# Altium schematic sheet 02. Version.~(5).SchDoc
size A3; DocumentNumber: 2; SheetNumber: 2; SheetTotal: 2
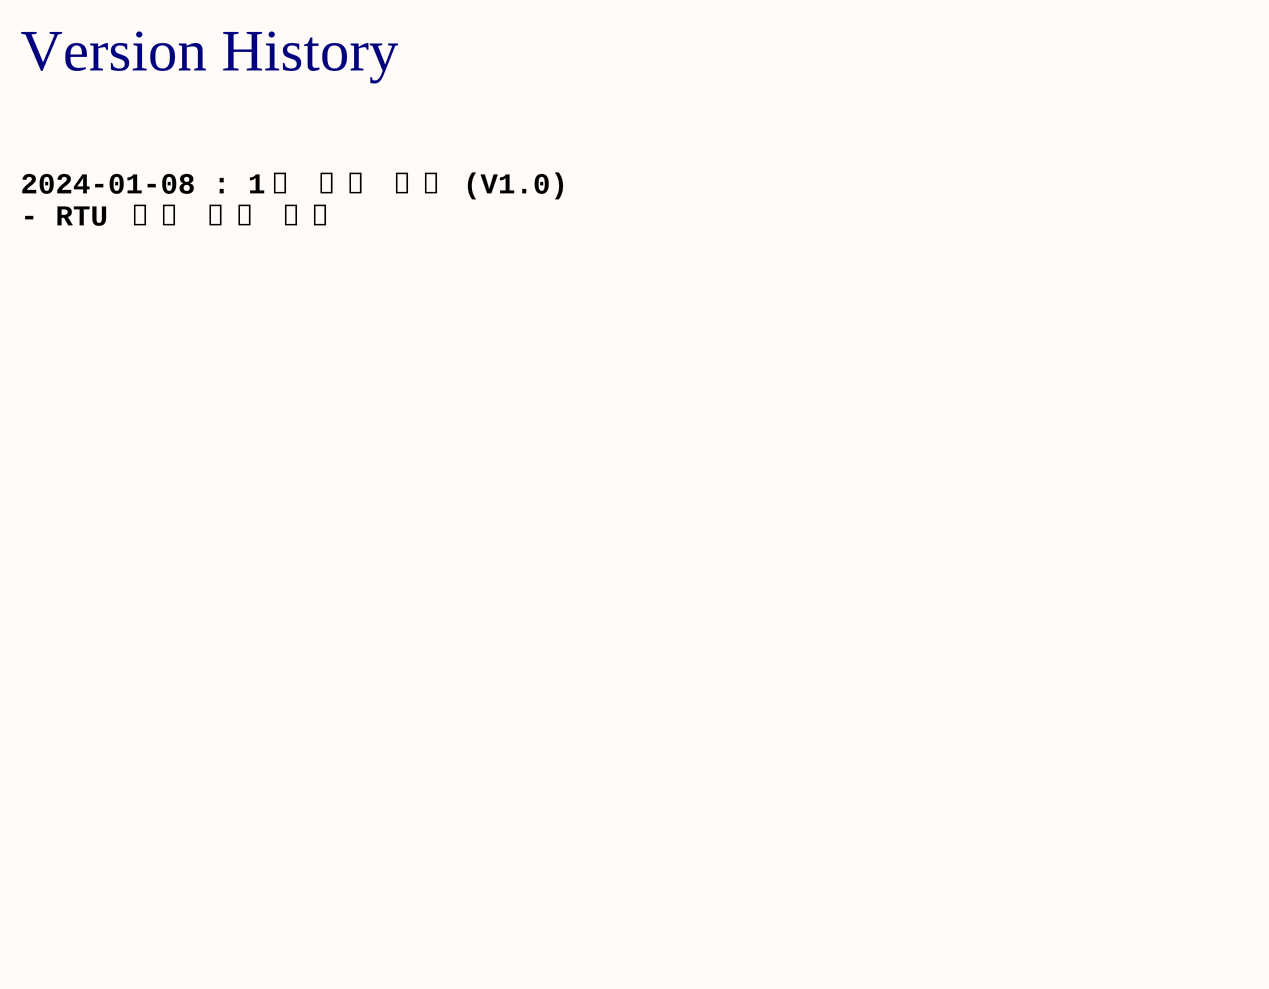
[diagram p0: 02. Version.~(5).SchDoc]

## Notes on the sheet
- Version History
- 2024-01-08 : 1차 회로 설계 (V1.0)
  - RTU 회로 설계 초안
